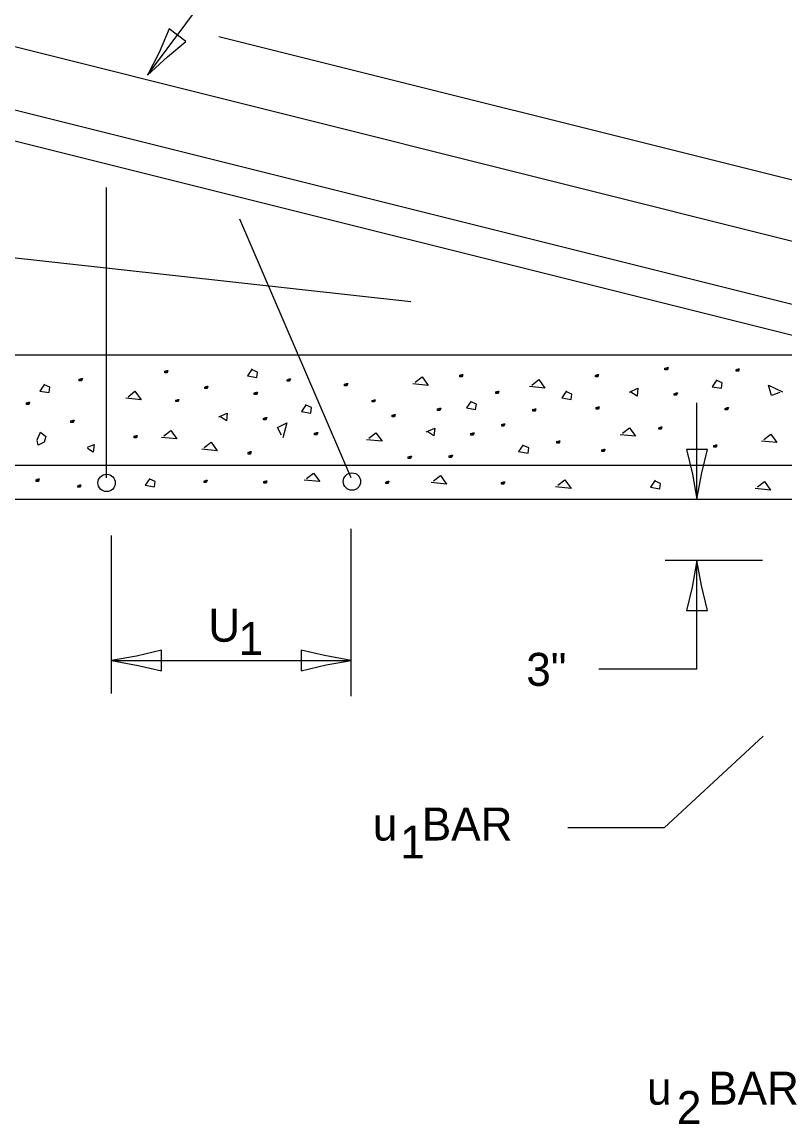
# Model space of a CAD drawing. Extents: x 2133490 to 2172050, y 2138301 to 2145980.
# Drawn here: x 2141183.6 to 2141322.5, y 2142118.4 to 2142319 of the extents above; entities that cross this region are included whole.
import ezdxf

# ---------------------------------------------------------------- set-up
doc = ezdxf.new("R2010")
doc.units = 0
for name, color, linetype in [('Level 63', 7, 'Continuous'), ('ROW_EX_Private Boundary Items', 7, 'Continuous'), ('ROW_PR_Notes', 7, 'Continuous'), ('Topo_Bridge Structures', 7, 'Continuous')]:
    doc.layers.add(name, color=color, linetype=linetype)

msp = doc.modelspace()

# ---------------------------------------------------------------- linework, layer by layer
at = {"layer": 'Level 63'}
for p, q in [((2141219.43, 2142316.39), (2141409.31, 2142268.92)), ((2141306.47, 2142232.1), (2141306.47, 2142249.66)), ((2141318.4, 2142220.97), (2141300.69, 2142220.97)), ((2141306.47, 2142201.17), (2141306.47, 2142220.97)), ((2141306.47, 2142201.17), (2141288.57, 2142201.17))]:
    msp.add_line(p, q, dxfattribs=at)
at = {"layer": 'ROW_EX_Private Boundary Items'}
for centre in [(2141198.98, 2142235.08), (2141243.65, 2142235.34)]:
    msp.add_circle(centre, 1.58, dxfattribs=at)
at = {"layer": 'ROW_PR_Notes'}
for p, q in [((2140787.94, 2142413.09), (2141406.68, 2142258.41)), ((2140785.24, 2142402.29), (2141403.98, 2142247.61)), ((2141402.63, 2142242.21), (2140783.89, 2142396.89)), ((2141206.42, 2142309.32), (2141236.16, 2142349.14)), ((2141254.37, 2142268.08), (2140799.13, 2142318.16)), ((2141198.97, 2142236.03), (2141198.97, 2142288.88)), ((2141243.5, 2142236.03), (2141223.25, 2142283.1)), ((2140599.86, 2142258.41), (2141360.78, 2142258.41)), ((2140576.59, 2142238.29), (2141407.11, 2142238.29)), ((2140825.08, 2142232.1), (2141349.25, 2142232.1)), ((2141243.5, 2142196.27), (2141243.5, 2142226.7)), ((2141199.84, 2142196.76), (2141199.84, 2142225.5)), ((2141199.84, 2142202.76), (2141243.5, 2142202.76)), ((2141318.54, 2142188.97), (2141300.47, 2142172.26)), ((2141300.47, 2142172.26), (2141282.98, 2142172.26))]:
    msp.add_line(p, q, dxfattribs=at)
for points in [[(2141209.69, 2142255.41), (2141209.98, 2142255.55), (2141209.98, 2142255.13), (2141209.84, 2142255.13), (2141209.55, 2142255.13), (2141209.55, 2142255.13), (2141209.55, 2142255.41), (2141209.98, 2142255.55), (2141210.12, 2142255.55), (2141209.98, 2142255.13), (2141209.84, 2142255.13), (2141209.84, 2142255.55)], [(2141225.45, 2142255.84), (2141224.61, 2142254.57), (2141226.3, 2142254.29), (2141226.44, 2142255.27), (2141225.45, 2142255.7)], [(2141263.42, 2142254.7), (2141263.7, 2142254.84), (2141263.7, 2142254.42), (2141263.56, 2142254.42), (2141263.28, 2142254.42), (2141263.28, 2142254.42), (2141263.28, 2142254.7), (2141263.7, 2142254.84), (2141263.84, 2142254.84), (2141263.7, 2142254.42), (2141263.56, 2142254.42), (2141263.56, 2142254.84)], [(2141288.12, 2142254.67), (2141288.4, 2142254.81), (2141288.4, 2142254.39), (2141288.26, 2142254.39), (2141287.98, 2142254.39), (2141287.98, 2142254.39), (2141287.98, 2142254.67), (2141288.4, 2142254.81), (2141288.54, 2142254.81), (2141288.4, 2142254.39), (2141288.26, 2142254.39), (2141288.26, 2142254.81)], [(2141300.78, 2142255.98), (2141301.07, 2142256.12), (2141301.07, 2142255.7), (2141300.92, 2142255.7), (2141300.64, 2142255.7), (2141300.64, 2142255.7), (2141300.64, 2142255.98), (2141301.07, 2142256.12), (2141301.21, 2142256.12), (2141301.07, 2142255.7), (2141300.92, 2142255.7), (2141300.92, 2142256.12)], [(2141313.73, 2142255.7), (2141314.01, 2142255.84), (2141314.01, 2142255.41), (2141313.87, 2142255.41), (2141313.59, 2142255.41), (2141313.59, 2142255.41), (2141313.59, 2142255.7), (2141314.01, 2142255.84), (2141314.15, 2142255.84), (2141314.01, 2142255.41), (2141313.87, 2142255.41), (2141313.87, 2142255.84)], [(2141187.67, 2142253.08), (2141186.83, 2142251.81), (2141188.52, 2142251.53), (2141188.66, 2142252.51), (2141187.67, 2142252.94)], [(2141194.14, 2142253.97), (2141194.43, 2142254.11), (2141194.43, 2142253.69), (2141194.28, 2142253.69), (2141194, 2142253.69), (2141194, 2142253.69), (2141194, 2142253.97), (2141194.43, 2142254.11), (2141194.57, 2142254.11), (2141194.43, 2142253.69), (2141194.28, 2142253.69), (2141194.28, 2142254.11)], [(2141216.98, 2142252.54), (2141217.26, 2142252.68), (2141217.26, 2142252.26), (2141217.12, 2142252.26), (2141216.84, 2142252.26), (2141216.84, 2142252.26), (2141216.84, 2142252.54), (2141217.26, 2142252.68), (2141217.4, 2142252.68), (2141217.26, 2142252.26), (2141217.12, 2142252.26), (2141217.12, 2142252.68)], [(2141232.01, 2142253.88), (2141232.29, 2142254.02), (2141232.29, 2142253.6), (2141232.15, 2142253.6), (2141231.87, 2142253.6), (2141231.87, 2142253.6), (2141231.87, 2142253.88), (2141232.29, 2142254.02), (2141232.43, 2142254.02), (2141232.29, 2142253.6), (2141232.15, 2142253.6), (2141232.15, 2142254.02)], [(2141242.46, 2142253.06), (2141242.74, 2142253.2), (2141242.74, 2142252.78), (2141242.6, 2142252.78), (2141242.31, 2142252.78), (2141242.31, 2142252.78), (2141242.31, 2142253.06), (2141242.74, 2142253.2), (2141242.88, 2142253.2), (2141242.74, 2142252.78), (2141242.6, 2142252.78), (2141242.6, 2142253.2)], [(2141255.15, 2142253.41), (2141256.41, 2142254.39), (2141257.54, 2142252.85), (2141254.72, 2142253.13)], [(2141276.4, 2142252.91), (2141277.67, 2142253.89), (2141278.79, 2142252.35), (2141275.98, 2142252.63)], [(2141310.07, 2142253.86), (2141309.22, 2142252.6), (2141310.92, 2142252.32), (2141311.06, 2142253.3), (2141310.07, 2142253.73)], [(2141321.54, 2142251.52), (2141320.01, 2142251.03), (2141319.48, 2142252.87), (2141322.03, 2142251.65)], [(2141202.88, 2142250.78), (2141204.14, 2142251.77), (2141205.27, 2142250.22), (2141202.45, 2142250.5)], [(2141226.01, 2142251.47), (2141226.3, 2142251.61), (2141226.3, 2142251.19), (2141226.15, 2142251.19), (2141225.87, 2142251.19), (2141225.87, 2142251.19), (2141225.87, 2142251.47), (2141226.3, 2142251.61), (2141226.44, 2142251.61), (2141226.3, 2142251.19), (2141226.15, 2142251.19), (2141226.15, 2142251.61)], [(2141269.96, 2142251.66), (2141270.24, 2142251.8), (2141270.24, 2142251.38), (2141270.1, 2142251.38), (2141269.82, 2142251.38), (2141269.82, 2142251.38), (2141269.82, 2142251.66), (2141270.24, 2142251.8), (2141270.38, 2142251.8), (2141270.24, 2142251.38), (2141270.1, 2142251.38), (2141270.1, 2142251.8)], [(2141282.72, 2142251.84), (2141281.87, 2142250.57), (2141283.56, 2142250.29), (2141283.7, 2142251.27), (2141282.72, 2142251.7)], [(2141294.17, 2142251.62), (2141295.72, 2142252.32), (2141295.58, 2142250.91), (2141294.45, 2142251.62)], [(2141302.47, 2142251.33), (2141302.76, 2142251.47), (2141302.76, 2142251.05), (2141302.61, 2142251.05), (2141302.33, 2142251.05), (2141302.33, 2142251.05), (2141302.33, 2142251.33), (2141302.76, 2142251.47), (2141302.9, 2142251.47), (2141302.76, 2142251.05), (2141302.61, 2142251.05), (2141302.61, 2142251.47)], [(2141184.52, 2142249.64), (2141184.8, 2142249.78), (2141184.8, 2142249.36), (2141184.66, 2142249.36), (2141184.38, 2142249.36), (2141184.38, 2142249.36), (2141184.38, 2142249.64), (2141184.8, 2142249.78), (2141184.95, 2142249.78), (2141184.8, 2142249.36), (2141184.66, 2142249.36), (2141184.66, 2142249.78)], [(2141211.72, 2142250.16), (2141212, 2142250.3), (2141212, 2142249.88), (2141211.86, 2142249.88), (2141211.58, 2142249.88), (2141211.58, 2142249.88), (2141211.58, 2142250.16), (2141212, 2142250.3), (2141212.14, 2142250.3), (2141212, 2142249.88), (2141211.86, 2142249.88), (2141211.86, 2142250.3)], [(2141235.3, 2142249.36), (2141234.45, 2142248.1), (2141236.15, 2142247.81), (2141236.29, 2142248.8), (2141235.3, 2142249.22)], [(2141247.45, 2142250.1), (2141247.74, 2142250.24), (2141247.74, 2142249.82), (2141247.6, 2142249.82), (2141247.31, 2142249.82), (2141247.31, 2142249.82), (2141247.31, 2142250.1), (2141247.74, 2142250.24), (2141247.88, 2142250.24), (2141247.74, 2142249.82), (2141247.6, 2142249.82), (2141247.6, 2142250.24)], [(2141259.38, 2142248.56), (2141259.67, 2142248.7), (2141259.67, 2142248.28), (2141259.52, 2142248.28), (2141259.24, 2142248.28), (2141259.24, 2142248.28), (2141259.24, 2142248.56), (2141259.67, 2142248.7), (2141259.81, 2142248.7), (2141259.67, 2142248.28), (2141259.52, 2142248.28), (2141259.52, 2142248.7)], [(2141265.33, 2142250), (2141264.48, 2142248.73), (2141266.17, 2142248.45), (2141266.31, 2142249.43), (2141265.33, 2142249.86)], [(2141276.72, 2142248.44), (2141277, 2142248.58), (2141277, 2142248.16), (2141276.86, 2142248.16), (2141276.58, 2142248.16), (2141276.58, 2142248.16), (2141276.58, 2142248.44), (2141277, 2142248.58), (2141277.14, 2142248.58), (2141277, 2142248.16), (2141276.86, 2142248.16), (2141276.86, 2142248.58)], [(2141288.24, 2142248.8), (2141288.52, 2142248.94), (2141288.52, 2142248.52), (2141288.38, 2142248.52), (2141288.1, 2142248.52), (2141288.1, 2142248.52), (2141288.1, 2142248.8), (2141288.52, 2142248.94), (2141288.66, 2142248.94), (2141288.52, 2142248.52), (2141288.38, 2142248.52), (2141288.38, 2142248.94)], [(2141311.76, 2142248.66), (2141312.04, 2142248.8), (2141312.04, 2142248.38), (2141311.9, 2142248.38), (2141311.62, 2142248.38), (2141311.62, 2142248.38), (2141311.62, 2142248.66), (2141312.04, 2142248.8), (2141312.18, 2142248.8), (2141312.04, 2142248.38), (2141311.9, 2142248.38), (2141311.9, 2142248.8)], [(2141219.4, 2142247.11), (2141220.95, 2142247.81), (2141220.81, 2142246.41), (2141219.69, 2142247.11)], [(2141227.7, 2142246.83), (2141227.99, 2142246.97), (2141227.99, 2142246.55), (2141227.85, 2142246.55), (2141227.56, 2142246.55), (2141227.56, 2142246.55), (2141227.56, 2142246.83), (2141227.99, 2142246.97), (2141228.12, 2142246.97), (2141227.99, 2142246.55), (2141227.85, 2142246.55), (2141227.85, 2142246.97)], [(2141251.11, 2142247.41), (2141251.39, 2142247.55), (2141251.39, 2142247.13), (2141251.25, 2142247.13), (2141250.97, 2142247.13), (2141250.97, 2142247.13), (2141250.97, 2142247.41), (2141251.39, 2142247.55), (2141251.53, 2142247.55), (2141251.39, 2142247.13), (2141251.25, 2142247.13), (2141251.25, 2142247.55)], [(2141192.62, 2142246.36), (2141192.9, 2142246.5), (2141192.9, 2142246.08), (2141192.76, 2142246.08), (2141192.48, 2142246.08), (2141192.48, 2142246.08), (2141192.48, 2142246.36), (2141192.9, 2142246.5), (2141193.04, 2142246.5), (2141192.9, 2142246.08), (2141192.76, 2142246.08), (2141192.76, 2142246.5)], [(2141209.39, 2142243.66), (2141210.65, 2142244.64), (2141211.77, 2142243.09), (2141208.96, 2142243.37)], [(2141230.83, 2142243.76), (2141230.08, 2142245.17), (2141231.8, 2142246.01), (2141231.04, 2142243.29)], [(2141257.16, 2142244.36), (2141258.71, 2142245.06), (2141258.57, 2142243.66), (2141257.44, 2142244.36)], [(2141271.05, 2142245.7), (2141271.33, 2142245.84), (2141271.33, 2142245.42), (2141271.19, 2142245.42), (2141270.91, 2142245.42), (2141270.91, 2142245.42), (2141270.91, 2142245.7), (2141271.33, 2142245.84), (2141271.47, 2142245.84), (2141271.33, 2142245.42), (2141271.19, 2142245.42), (2141271.19, 2142245.84)], [(2141292.91, 2142244.16), (2141294.17, 2142245.14), (2141295.3, 2142243.59), (2141292.48, 2142243.87)], [(2141299.66, 2142245.14), (2141299.94, 2142245.28), (2141299.94, 2142244.86), (2141299.8, 2142244.86), (2141299.52, 2142244.86), (2141299.52, 2142244.86), (2141299.52, 2142245.14), (2141299.94, 2142245.28), (2141300.08, 2142245.28), (2141299.94, 2142244.86), (2141299.8, 2142244.86), (2141299.8, 2142245.28)], [(2141186.34, 2142242.95), (2141186.91, 2142244.35), (2141187.9, 2142243.51), (2141187.61, 2142242.52), (2141186.49, 2142241.96), (2141186.34, 2142242.8)], [(2141204.11, 2142243.57), (2141204.4, 2142243.71), (2141204.4, 2142243.28), (2141204.25, 2142243.28), (2141203.97, 2142243.28), (2141203.97, 2142243.28), (2141203.97, 2142243.57), (2141204.4, 2142243.71), (2141204.54, 2142243.71), (2141204.4, 2142243.28), (2141204.25, 2142243.28), (2141204.25, 2142243.71)], [(2141236.99, 2142244.15), (2141237.27, 2142244.29), (2141237.27, 2142243.87), (2141237.13, 2142243.87), (2141236.85, 2142243.87), (2141236.85, 2142243.87), (2141236.85, 2142244.15), (2141237.27, 2142244.29), (2141237.41, 2142244.29), (2141237.27, 2142243.87), (2141237.13, 2142243.87), (2141237.13, 2142244.29)], [(2141246.74, 2142243.24), (2141248, 2142244.23), (2141249.13, 2142242.68), (2141246.31, 2142242.96)], [(2141265.47, 2142244.08), (2141265.74, 2142244.22), (2141265.74, 2142243.8), (2141265.61, 2142243.8), (2141265.32, 2142243.8), (2141265.32, 2142243.8), (2141265.32, 2142244.08), (2141265.74, 2142244.22), (2141265.89, 2142244.22), (2141265.74, 2142243.8), (2141265.61, 2142243.8), (2141265.61, 2142244.22)], [(2141281.09, 2142242.6), (2141281.37, 2142242.75), (2141281.37, 2142242.32), (2141281.23, 2142242.32), (2141280.95, 2142242.32), (2141280.95, 2142242.32), (2141280.95, 2142242.6), (2141281.37, 2142242.75), (2141281.51, 2142242.75), (2141281.37, 2142242.32), (2141281.23, 2142242.32), (2141281.23, 2142242.75)], [(2141318.63, 2142242.98), (2141319.9, 2142243.96), (2141321.02, 2142242.42), (2141318.2, 2142242.7)], [(2141195.49, 2142241.57), (2141196.68, 2142242.11), (2141196.54, 2142240.7), (2141195.49, 2142241.36)], [(2141216.74, 2142241.52), (2141218, 2142242.5), (2141219.13, 2142240.95), (2141216.31, 2142241.23)], [(2141224.89, 2142240.64), (2141225.17, 2142240.78), (2141225.17, 2142240.35), (2141225.03, 2142240.35), (2141224.75, 2142240.35), (2141224.75, 2142240.35), (2141224.75, 2142240.64), (2141225.17, 2142240.78), (2141225.31, 2142240.78), (2141225.17, 2142240.35), (2141225.03, 2142240.35), (2141225.03, 2142240.78)], [(2141274.85, 2142242.05), (2141274, 2142240.79), (2141275.7, 2142240.51), (2141275.83, 2142241.49), (2141274.85, 2142241.91)], [(2141289.29, 2142241.1), (2141289.57, 2142241.24), (2141289.57, 2142240.82), (2141289.43, 2142240.82), (2141289.15, 2142240.82), (2141289.15, 2142240.82), (2141289.15, 2142241.1), (2141289.57, 2142241.24), (2141289.71, 2142241.24), (2141289.57, 2142240.82), (2141289.43, 2142240.82), (2141289.43, 2142241.24)], [(2141309.68, 2142241.9), (2141309.96, 2142242.04), (2141309.96, 2142241.62), (2141309.82, 2142241.62), (2141309.54, 2142241.62), (2141309.54, 2142241.62), (2141309.54, 2142241.9), (2141309.96, 2142242.04), (2141310.1, 2142242.04), (2141309.96, 2142241.62), (2141309.82, 2142241.62), (2141309.82, 2142242.04)], [(2141254.04, 2142239.82), (2141254.33, 2142239.96), (2141254.33, 2142239.53), (2141254.18, 2142239.53), (2141253.9, 2142239.53), (2141253.9, 2142239.53), (2141253.9, 2142239.82), (2141254.33, 2142239.96), (2141254.47, 2142239.96), (2141254.33, 2142239.53), (2141254.18, 2142239.53), (2141254.18, 2142239.96)], [(2141261.51, 2142240), (2141261.79, 2142240.14), (2141261.79, 2142239.72), (2141261.65, 2142239.72), (2141261.37, 2142239.72), (2141261.37, 2142239.72), (2141261.37, 2142240), (2141261.79, 2142240.14), (2141261.93, 2142240.14), (2141261.79, 2142239.72), (2141261.65, 2142239.72), (2141261.65, 2142240.14)], [(2141235.39, 2142235.9), (2141236.66, 2142236.88), (2141237.78, 2142235.34), (2141234.97, 2142235.61)], [(2141186.27, 2142235.66), (2141186.56, 2142235.8), (2141186.56, 2142235.37), (2141186.42, 2142235.37), (2141186.13, 2142235.37), (2141186.13, 2142235.37), (2141186.13, 2142235.66), (2141186.56, 2142235.8), (2141186.69, 2142235.8), (2141186.56, 2142235.37), (2141186.42, 2142235.37), (2141186.42, 2142235.8)], [(2141193.88, 2142234.57), (2141194.17, 2142234.71), (2141194.17, 2142234.29), (2141194.02, 2142234.29), (2141193.74, 2142234.29), (2141193.74, 2142234.29), (2141193.74, 2142234.57), (2141194.17, 2142234.71), (2141194.31, 2142234.71), (2141194.17, 2142234.29), (2141194.02, 2142234.29), (2141194.02, 2142234.71)], [(2141206.85, 2142235.92), (2141206, 2142234.65), (2141207.69, 2142234.37), (2141207.83, 2142235.36), (2141206.85, 2142235.78)], [(2141216.85, 2142235.43), (2141217.13, 2142235.57), (2141217.13, 2142235.15), (2141216.99, 2142235.15), (2141216.71, 2142235.15), (2141216.71, 2142235.15), (2141216.71, 2142235.43), (2141217.13, 2142235.57), (2141217.27, 2142235.57), (2141217.13, 2142235.15), (2141216.99, 2142235.15), (2141216.99, 2142235.57)], [(2141227.72, 2142235.32), (2141228, 2142235.46), (2141228, 2142235.03), (2141227.86, 2142235.03), (2141227.58, 2142235.03), (2141227.58, 2142235.03), (2141227.58, 2142235.32), (2141228, 2142235.46), (2141228.14, 2142235.46), (2141228, 2142235.03), (2141227.86, 2142235.03), (2141227.86, 2142235.46)], [(2141249.95, 2142235.25), (2141250.23, 2142235.38), (2141250.23, 2142234.96), (2141250.09, 2142234.96), (2141249.81, 2142234.96), (2141249.81, 2142234.96), (2141249.81, 2142235.25), (2141250.23, 2142235.38), (2141250.37, 2142235.38), (2141250.23, 2142234.96), (2141250.09, 2142234.96), (2141250.09, 2142235.38)], [(2141258.5, 2142235.44), (2141259.77, 2142236.42), (2141260.89, 2142234.87), (2141258.07, 2142235.15)], [(2141271.04, 2142235.14), (2141271.32, 2142235.27), (2141271.32, 2142234.85), (2141271.18, 2142234.85), (2141270.9, 2142234.85), (2141270.9, 2142234.85), (2141270.9, 2142235.14), (2141271.32, 2142235.27), (2141271.46, 2142235.27), (2141271.32, 2142234.85), (2141271.18, 2142234.85), (2141271.18, 2142235.27)], [(2141281.15, 2142234.65), (2141282.42, 2142235.63), (2141283.55, 2142234.08), (2141280.73, 2142234.37)], [(2141298.85, 2142235.57), (2141298, 2142234.3), (2141299.7, 2142234.02), (2141299.84, 2142235), (2141298.85, 2142235.43)], [(2141317.49, 2142234.35), (2141318.75, 2142235.33), (2141319.88, 2142233.78), (2141317.06, 2142234.06)]]:
    msp.add_lwpolyline(points, dxfattribs=at)
at = {"layer": 'Topo_Bridge Structures'}
for points in [[(2141213.39, 2142315.47), (2141211.87, 2142316.62), (2141210.35, 2142317.75), (2141208.52, 2142313.44), (2141206.42, 2142309.32), (2141210.04, 2142312.68)], [(2141308.37, 2142241.2), (2141306.47, 2142241.2), (2141304.57, 2142241.2), (2141305.68, 2142236.65), (2141306.47, 2142232.1), (2141307.35, 2142236.95)], [(2141304.57, 2142211.87), (2141306.47, 2142211.86), (2141308.37, 2142211.86), (2141307.26, 2142216.42), (2141306.47, 2142220.97), (2141305.59, 2142216.11)], [(2141208.94, 2142200.85), (2141208.95, 2142202.76), (2141208.95, 2142204.66), (2141204.39, 2142203.54), (2141199.84, 2142202.76), (2141204.7, 2142201.87)], [(2141234.4, 2142204.66), (2141234.39, 2142202.76), (2141234.39, 2142200.85), (2141238.95, 2142201.97), (2141243.5, 2142202.76), (2141238.64, 2142203.64)]]:
    msp.add_lwpolyline(points, close=True, dxfattribs=at)

# ---------------------------------------------------------------- texts
at = {"layer": 'Level 63'}
for s, p in [('U', (2141217.5, 2142206.17)), ('1', (2141222.99, 2142203.75)), ('3"', (2141275.39, 2142198.14)), ('u  BAR', (2141247.45, 2142169.98)), ('1', (2141252.43, 2142166.71)), ('u   BAR', (2141297.37, 2142121.89)), ('2', (2141302.81, 2142118.37))]:
    msp.add_text(s, height=6, dxfattribs=at).set_placement(p)

doc.saveas('drawing.dxf')
